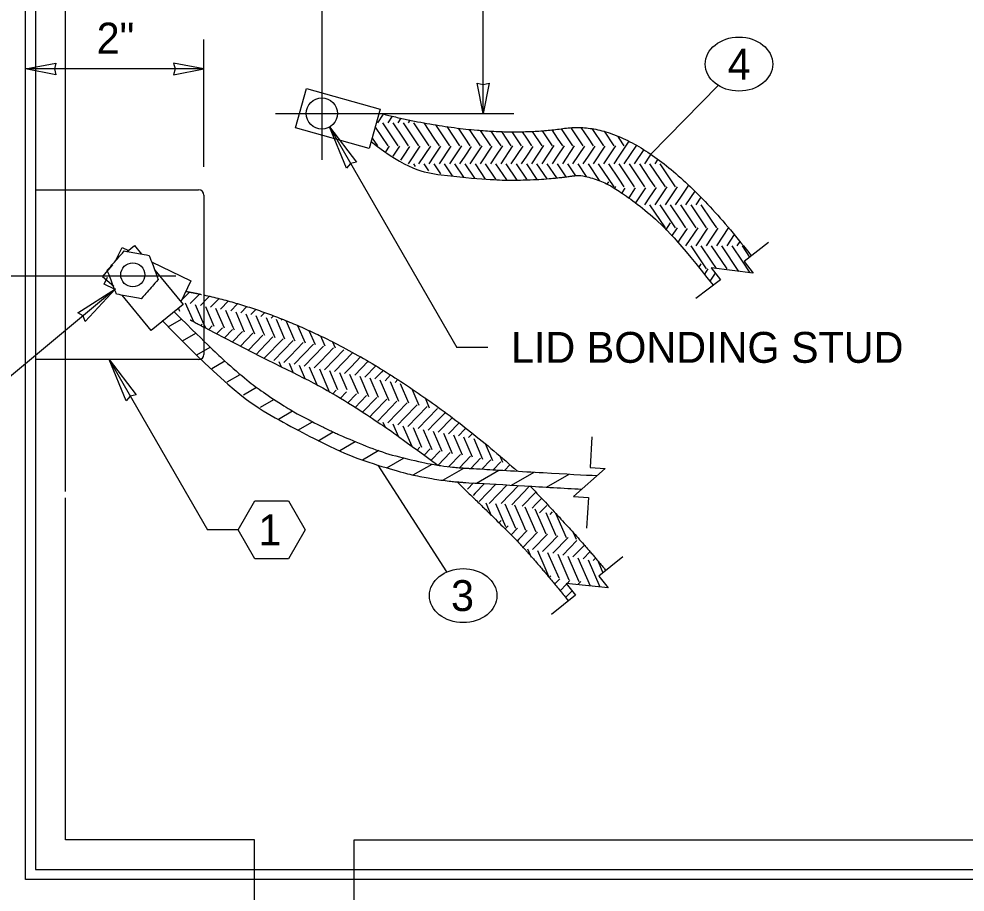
# Model space of a CAD drawing. Extents: x 99862 to 103151, y 100000 to 102076.
# Drawn here: x 101148.1 to 101638.2, y 101390 to 101842.6 of the extents above; entities that cross this region are included whole.
import ezdxf

# ---------------------------------------------------------------- set-up
doc = ezdxf.new("R2010")
doc.units = 0
for name, color, linetype in [('Level 15', 7, 'Continuous'), ('Level 16', 7, 'Continuous'), ('Level 18', 7, 'Continuous'), ('Level 2', 7, 'Continuous'), ('Level 20', 7, 'Continuous'), ('Level 26', 7, 'Continuous'), ('Level 28', 7, 'Continuous'), ('Level 3', 7, 'Continuous'), ('Level 7', 7, 'Continuous')]:
    doc.layers.add(name, color=color, linetype=linetype)

msp = doc.modelspace()

# ---------------------------------------------------------------- linework, layer by layer
at = {"layer": 'Level 15'}
for p, q in [((101388.54, 101793.52), (101388.54, 101912.13)), ((101305.14, 101769.47), (101305.14, 101888.08)), ((101243.99, 101765.95), (101243.99, 101831.95)), ((101243.99, 101816.61), (101151.56, 101816.61)), ((101510.28, 101808.11), (101475.36, 101772.46)), ((101280.97, 101793.52), (101404.54, 101793.52)), ((101309.05, 101786.55), (101375, 101672.31)), ((101229.35, 101709.29), (100983.06, 101709.29)), ((101198.13, 101702.58), (101041.53, 101572.52)), ((101391, 101672.31), (101375, 101672.31)), ((101194.82, 101665.95), (101245.74, 101577.75)), ((101369.79, 101555.93), (101334.19, 101611.25)), ((101261.74, 101577.75), (101245.74, 101577.75))]:
    msp.add_line(p, q, dxfattribs=at)
for points in [[(101151.56, 101816.61), (101167.29, 101819.69), (101166.56, 101816.61), (101167.29, 101813.52)], [(101243.99, 101816.61), (101228.27, 101819.69), (101229, 101816.61), (101228.27, 101813.52)], [(101388.54, 101793.52), (101385.45, 101809.24), (101388.54, 101808.52), (101391.62, 101809.24)], [(101309.05, 101786.55), (101323.04, 101768.27), (101319.93, 101767.69), (101317.88, 101765.28)], [(101198.13, 101702.58), (101182.47, 101685.7), (101181.38, 101688.67), (101178.66, 101690.29)], [(101194.82, 101665.95), (101208.82, 101647.67), (101205.71, 101647.09), (101203.65, 101644.68)]]:
    msp.add_lwpolyline(points, close=True, dxfattribs=at)
for points in [[(101536.39, 101726.6), (101523.71, 101716.84), (101528.44, 101710.7), (101506.72, 101713.52), (101511.44, 101707.39), (101498.77, 101697.62)], [(101444.93, 101626.01), (101444.01, 101610.04), (101451.74, 101609.59), (101435.39, 101595.02), (101443.12, 101594.58), (101442.2, 101578.6)], [(101460.86, 101563.79), (101448.42, 101553.72), (101453.3, 101547.7), (101431.52, 101549.99), (101436.39, 101543.97), (101423.96, 101533.9)]]:
    msp.add_lwpolyline(points, dxfattribs=at)
at = {"layer": 'Level 16'}
for points in [[(101204.21, 101722.02), (101207.99, 101725.12), (101211.64, 101720.67)], [(101197.33, 101703.91), (101191.51, 101708.85), (101196.79, 101715.08)], [(101218.48, 101712.35), (101233.15, 101694.47), (101216.72, 101680.98), (101201.66, 101699.34)]]:
    msp.add_lwpolyline(points, dxfattribs=at)
at = {"layer": 'Level 18'}
for p, q in [((101225.47, 101683.02), (101232.33, 101686.99)), ((101232.79, 101675.71), (101239.73, 101679.71)), ((101240.3, 101668.5), (101247.18, 101672.47)), ((101248.03, 101661.41), (101254.76, 101665.3)), ((101256.05, 101654.49), (101262.71, 101658.34)), ((101264.41, 101647.77), (101271.18, 101651.68)), ((101273.22, 101641.31), (101280.23, 101645.36)), ((101282.59, 101635.17), (101289.89, 101639.39)), ((101292.58, 101629.39), (101300.16, 101633.77)), ((101303.16, 101623.96), (101310.96, 101628.46)), ((101314.29, 101618.84), (101322.36, 101623.5)), ((101326.08, 101614.1), (101334.51, 101618.96)), ((101338.69, 101609.83), (101347.63, 101614.99)), ((101352.39, 101606.19), (101362.1, 101611.8)), ((101367.62, 101603.44), (101378.6, 101609.78)), ((101385.07, 101601.97), (101396.77, 101608.72)), ((101403.26, 101600.92), (101414.96, 101607.68)), ((101421.44, 101599.87), (101433.17, 101606.64))]:
    msp.add_line(p, q, dxfattribs=at)
for points in [[(101228.69, 101690.57), (101247.5, 101672.03), (101254.17, 101665.6), (101267.28, 101654.42), (101273.71, 101649.65), (101286.44, 101641.27), (101292.74, 101637.65), (101302.19, 101632.7), (101305.34, 101631.13), (101311.6, 101628.14), (101314.72, 101626.73), (101330.23, 101620.06), (101342.42, 101616.02), (101360.42, 101611.99), (101366.36, 101610.99), (101373.73, 101610.18), (101375.21, 101610.04), (101377.03, 101609.89), (101377.4, 101609.86), (101377.95, 101609.82), (101378.22, 101609.8), (101378.51, 101609.78), (101378.7, 101609.77), (101378.8, 101609.76), (101379.22, 101609.74), (101379.64, 101609.71), (101380.3, 101609.67), (101380.61, 101609.66), (101383.48, 101609.49), (101420.86, 101607.33), (101441.32, 101606.15), (101447.6, 101605.9)], [(101222.31, 101686.26), (101257.42, 101650.1), (101278.28, 101636.57), (101312.51, 101619.16), (101326.13, 101613.58), (101346.34, 101607.54), (101353.04, 101605.91), (101363.04, 101604.08), (101366.36, 101603.58), (101371.33, 101602.97), (101373.8, 101602.71), (101376.69, 101602.48), (101377.92, 101602.39), (101378.75, 101602.34), (101379.23, 101602.31), (101410.06, 101600.53), (101430.09, 101599.37), (101439.65, 101598.82)]]:
    msp.add_open_spline(points, degree=3, dxfattribs=at)
at = {"layer": 'Level 2'}
for p, q in [((101172.19, 101597.59), (101172.19, 101912.13)), ((101172.19, 101417.13), (101172.19, 101594.38)), ((101270.16, 101417.13), (101172.19, 101417.13)), ((101270.16, 101353.87), (101270.16, 101417.13)), ((101321.72, 101417.13), (101868.28, 101417.13)), ((101321.72, 101353.87), (101321.72, 101417.13))]:
    msp.add_line(p, q, dxfattribs=at)
at = {"layer": 'Level 20'}
msp.add_lwpolyline([(101261.74, 101577.75), (101270.4, 101592.75), (101287.72, 101592.75), (101296.37, 101577.75), (101287.72, 101562.76), (101270.4, 101562.76), (101261.74, 101577.75)], dxfattribs=at)
for centre in [(101521.08, 101819.13), (101378.24, 101543.67)]:
    msp.add_ellipse(centre, major_axis=(-17.5, 0), ratio=0.8, dxfattribs=at)
at = {"layer": 'Level 26'}
for p, q in [((101336.82, 101793.23), (101333.84, 101788.76)), ((101341.41, 101792.13), (101339.16, 101788.76)), ((101346.03, 101791.08), (101344.48, 101788.76)), ((101350.68, 101790.08), (101349.8, 101788.76)), ((101332.71, 101786.47), (101339.16, 101776.79)), ((101336.5, 101788.76), (101344.48, 101776.79)), ((101341.82, 101788.76), (101347.14, 101780.78)), ((101347.14, 101788.76), (101355.12, 101776.79)), ((101352.46, 101788.76), (101360.44, 101776.79)), ((101357.83, 101788.68), (101363.1, 101780.78)), ((101363.85, 101787.63), (101371.08, 101776.79)), ((101369.78, 101786.72), (101376.4, 101776.79)), ((101375.62, 101785.94), (101379.06, 101780.78)), ((101381.37, 101785.29), (101387.04, 101776.79)), ((101424.13, 101784.99), (101426.94, 101780.78)), ((101429.06, 101785.57), (101434.92, 101776.79)), ((101433.98, 101786.18), (101440.24, 101776.79)), ((101439.24, 101786.26), (101442.9, 101780.78)), ((101444.95, 101785.69), (101450.88, 101776.79)), ((101331.13, 101780.85), (101331.18, 101780.78)), ((101331.18, 101780.78), (101333.84, 101776.79)), ((101347.14, 101780.78), (101349.8, 101776.79)), ((101363.1, 101780.78), (101365.76, 101776.79)), ((101379.06, 101780.78), (101381.72, 101776.79)), ((101387.03, 101784.78), (101392.36, 101776.79)), ((101392.6, 101784.4), (101395.02, 101780.78)), ((101395.02, 101780.78), (101397.68, 101776.79)), ((101398.09, 101784.16), (101403, 101776.79)), ((101403.48, 101784.05), (101408.32, 101776.79)), ((101408.78, 101784.08), (101410.98, 101780.78)), ((101410.98, 101780.78), (101413.64, 101776.79)), ((101413.99, 101784.25), (101418.96, 101776.79)), ((101419.1, 101784.55), (101424.28, 101776.79)), ((101426.94, 101780.78), (101429.6, 101776.79)), ((101442.9, 101780.78), (101445.56, 101776.79)), ((101451.19, 101784.31), (101456.2, 101776.79)), ((101458.1, 101781.91), (101458.86, 101780.78)), ((101458.86, 101780.78), (101461.52, 101776.79)), ((101339.96, 101776.66), (101338.02, 101773.74)), ((101345.24, 101776.6), (101341.8, 101771.44)), ((101350.49, 101776.5), (101347.14, 101771.47)), ((101355.84, 101776.54), (101349.8, 101767.48)), ((101361.23, 101776.65), (101355.12, 101767.48)), ((101366.48, 101776.54), (101363.1, 101771.47)), ((101371.89, 101776.68), (101365.76, 101767.48)), ((101377.33, 101776.86), (101371.08, 101767.48)), ((101382.39, 101776.46), (101379.06, 101771.47)), ((101387.89, 101776.74), (101381.72, 101767.48)), ((101393.11, 101776.58), (101387.04, 101767.48)), ((101398.55, 101776.76), (101395.02, 101771.47)), ((101403.85, 101776.73), (101397.68, 101767.48)), ((101409.1, 101776.63), (101403, 101767.48)), ((101414.34, 101776.51), (101410.98, 101771.47)), ((101419.91, 101776.88), (101413.64, 101767.48)), ((101425.22, 101776.87), (101418.96, 101767.48)), ((101430.51, 101776.82), (101426.94, 101771.47)), ((101435.81, 101776.79), (101429.6, 101767.48)), ((101441.01, 101776.61), (101434.92, 101767.48)), ((101446.35, 101776.65), (101442.9, 101771.47)), ((101451.69, 101776.67), (101445.56, 101767.48)), ((101457.12, 101776.83), (101450.88, 101767.48)), ((101464.02, 101779.21), (101458.86, 101771.47)), ((101467.94, 101777.12), (101461.52, 101767.48)), ((101347.14, 101771.47), (101345.73, 101769.36)), ((101363.1, 101771.47), (101360.44, 101767.48)), ((101379.06, 101771.47), (101376.4, 101767.48)), ((101395.02, 101771.47), (101392.36, 101767.48)), ((101410.98, 101771.47), (101408.32, 101767.48)), ((101426.94, 101771.47), (101424.28, 101767.48)), ((101442.9, 101771.47), (101440.24, 101767.48)), ((101458.86, 101771.47), (101456.2, 101767.48)), ((101471.74, 101774.83), (101466.84, 101767.48)), ((101474.82, 101771.47), (101472.16, 101767.48)), ((101475.44, 101772.4), (101474.82, 101771.47)), ((101352.46, 101767.48), (101353.42, 101766.03)), ((101357.78, 101767.48), (101360.21, 101763.84)), ((101363.1, 101767.48), (101366.55, 101762.31)), ((101368.42, 101767.48), (101372.58, 101761.23)), ((101373.74, 101767.48), (101378.41, 101760.48)), ((101379.06, 101767.48), (101384.09, 101759.94)), ((101384.38, 101767.48), (101389.68, 101759.53)), ((101389.7, 101767.48), (101395.02, 101759.5)), ((101395.02, 101767.48), (101400.61, 101759.09)), ((101400.34, 101767.48), (101405.96, 101759.05)), ((101405.66, 101767.48), (101410.98, 101759.5)), ((101410.98, 101767.48), (101416.4, 101759.34)), ((101416.3, 101767.48), (101421.51, 101759.67)), ((101421.62, 101767.48), (101426.53, 101760.12)), ((101426.94, 101767.48), (101431.47, 101760.69)), ((101432.26, 101767.48), (101436.38, 101761.29)), ((101437.58, 101767.48), (101442.02, 101760.82)), ((101442.9, 101767.48), (101448.73, 101758.73)), ((101448.22, 101767.48), (101456.2, 101755.51)), ((101453.54, 101767.48), (101458.86, 101759.5)), ((101458.86, 101767.48), (101466.84, 101755.51)), ((101464.18, 101767.48), (101472.16, 101755.51)), ((101469.5, 101767.48), (101474.82, 101759.5)), ((101474.82, 101767.48), (101482.8, 101755.51)), ((101479.06, 101769.85), (101477.48, 101767.48)), ((101480.14, 101767.48), (101488.12, 101755.51)), ((101395.02, 101759.5), (101395.19, 101759.24)), ((101410.98, 101759.5), (101411.22, 101759.13)), ((101453.54, 101758.17), (101452.7, 101756.91)), ((101457.2, 101755.68), (101456.6, 101754.78)), ((101458.86, 101759.5), (101461.52, 101755.51)), ((101474.82, 101759.5), (101477.48, 101755.51)), ((101483.67, 101755.48), (101477.48, 101746.2)), ((101489, 101755.5), (101482.8, 101746.2)), ((101494.96, 101756.46), (101490.78, 101750.19)), ((101461.93, 101754.79), (101460.36, 101752.43)), ((101467.4, 101755.02), (101463.98, 101749.89)), ((101472.68, 101754.96), (101467.51, 101747.21)), ((101478.12, 101755.14), (101474.82, 101750.19)), ((101498.2, 101753.34), (101493.44, 101746.2)), ((101474.82, 101750.19), (101472.16, 101746.2)), ((101474.82, 101746.2), (101482.8, 101734.23)), ((101480.14, 101746.2), (101488.12, 101734.23)), ((101485.46, 101746.2), (101490.78, 101738.22)), ((101490.78, 101750.19), (101488.12, 101746.2)), ((101490.78, 101746.2), (101498.76, 101734.23)), ((101496.1, 101746.2), (101504.08, 101734.23)), ((101501.39, 101750.14), (101498.76, 101746.2)), ((101501.42, 101746.2), (101506.74, 101738.22)), ((101485.46, 101736.89), (101482.97, 101733.15)), ((101490.78, 101738.22), (101493.44, 101734.23)), ((101506.74, 101738.22), (101509.4, 101734.23)), ((101488.99, 101734.2), (101486.12, 101729.9)), ((101494.17, 101734), (101490.78, 101728.91)), ((101499.7, 101734.31), (101493.44, 101724.92)), ((101504.86, 101734.06), (101498.76, 101724.92)), ((101510.19, 101734.08), (101506.74, 101728.91)), ((101515.7, 101734.37), (101509.4, 101724.92)), ((101490.78, 101728.91), (101489.22, 101726.57)), ((101506.74, 101728.91), (101504.08, 101724.92)), ((101518.66, 101730.83), (101514.72, 101724.92)), ((101521.58, 101727.23), (101520.04, 101724.92)), ((101496.1, 101724.92), (101504.08, 101712.95)), ((101501.42, 101724.92), (101506.74, 101716.94)), ((101506.74, 101724.92), (101514.72, 101712.95)), ((101512.06, 101724.92), (101520.88, 101711.68)), ((101517.38, 101724.92), (101522.7, 101716.94)), ((101522.7, 101724.92), (101526.6, 101719.06)), ((101506.74, 101716.94), (101509.23, 101713.2)), ((101522.7, 101716.94), (101526.71, 101710.93)), ((101501.42, 101715.61), (101500.24, 101713.84)), ((101504.99, 101712.99), (101503.16, 101710.24)), ((101506.74, 101707.63), (101506.05, 101706.59)), ((101508.84, 101710.77), (101506.74, 101707.63)), ((101236.53, 101701), (101232.24, 101696.55)), ((101241.69, 101699.97), (101236.88, 101695)), ((101245.45, 101697.49), (101242.12, 101694.04)), ((101246.78, 101698.87), (101245.45, 101697.49)), ((101251.8, 101697.69), (101247.35, 101693.09)), ((101230.74, 101692.49), (101231.31, 101691.15)), ((101234.27, 101695.47), (101238.48, 101685.73)), ((101239.5, 101694.52), (101243.31, 101685.72)), ((101244.74, 101693.57), (101249.15, 101683.37)), ((101249.97, 101692.62), (101254.38, 101682.41)), ((101256.7, 101696.4), (101252.59, 101692.14)), ((101261.15, 101694.64), (101257.82, 101691.19)), ((101261.48, 101694.98), (101261.15, 101694.64)), ((101266.23, 101693.53), (101263.06, 101690.24)), ((101270.9, 101691.99), (101268.29, 101689.29)), ((101255.2, 101691.67), (101259.01, 101682.86)), ((101260.44, 101690.71), (101264.87, 101680.46)), ((101265.67, 101689.76), (101270.15, 101679.42)), ((101270.91, 101688.81), (101274.71, 101680.01)), ((101275.51, 101690.39), (101273.52, 101688.34)), ((101276.14, 101687.86), (101280.62, 101677.51)), ((101280.05, 101688.72), (101278.76, 101687.38)), ((101281.38, 101686.91), (101285.77, 101676.75)), ((101284.52, 101686.98), (101283.99, 101686.43)), ((101243.07, 101684.41), (101242.35, 101683.66)), ((101243.31, 101685.72), (101244.75, 101682.38)), ((101248.31, 101683.46), (101246.42, 101681.5)), ((101253.54, 101682.51), (101250.51, 101679.37)), ((101259.01, 101682.86), (101259.61, 101681.48)), ((101286.61, 101685.96), (101290.42, 101677.15)), ((101292.4, 101683.72), (101296.32, 101674.65)), ((101258.77, 101681.55), (101254.61, 101677.24)), ((101264.01, 101680.6), (101258.73, 101675.13)), ((101269.24, 101679.65), (101262.85, 101673.03)), ((101274.48, 101678.7), (101266.98, 101670.93)), ((101279.71, 101677.75), (101273.05, 101670.85)), ((101274.71, 101680.01), (101275.31, 101678.62)), ((101290.42, 101677.15), (101291.02, 101675.75)), ((101298.37, 101681.07), (101301.51, 101673.82)), ((101304.42, 101678.23), (101306.12, 101674.3)), ((101284.94, 101676.8), (101275.24, 101666.75)), ((101290.18, 101675.84), (101280.19, 101665.49)), ((101295.41, 101674.89), (101288.75, 101667.99)), ((101300.65, 101673.94), (101290.66, 101663.59)), ((101305.88, 101672.99), (101295.89, 101662.64)), ((101306.12, 101674.3), (101306.63, 101673.13)), ((101310.55, 101675.19), (101311.94, 101672)), ((101273.05, 101670.85), (101271.11, 101668.84)), ((101288.75, 101667.99), (101285.42, 101664.54)), ((101311.12, 101672.04), (101304.45, 101665.14)), ((101316.35, 101671.09), (101306.36, 101660.74)), ((101321.08, 101669.62), (101311.59, 101659.79)), ((101325.08, 101667.38), (101320.16, 101662.28)), ((101282.8, 101665.02), (101283.98, 101662.29)), ((101288.04, 101664.07), (101290.2, 101659.08)), ((101293.27, 101663.12), (101296.44, 101655.79)), ((101304.45, 101665.14), (101301.12, 101661.69)), ((101329.03, 101665.11), (101322.06, 101657.88)), ((101332.95, 101662.79), (101327.29, 101656.93)), ((101298.51, 101662.16), (101302.31, 101653.36)), ((101303.74, 101661.21), (101309.08, 101648.88)), ((101308.97, 101660.26), (101313.23, 101650.42)), ((101314.21, 101659.31), (101318.02, 101650.51)), ((101320.16, 101662.28), (101316.83, 101658.83)), ((101319.44, 101658.36), (101323.78, 101648.33)), ((101335.86, 101659.43), (101332.53, 101655.98)), ((101336.83, 101660.43), (101335.86, 101659.43)), ((101340.67, 101658.04), (101337.76, 101655.03)), ((101302.31, 101653.36), (101302.73, 101652.4)), ((101324.68, 101657.41), (101329.21, 101646.92)), ((101329.91, 101656.46), (101334.18, 101646.58)), ((101335.15, 101655.5), (101339.75, 101644.87)), ((101340.38, 101654.55), (101344.74, 101644.47)), ((101344.48, 101655.61), (101343, 101654.08)), ((101345.61, 101653.6), (101349.97, 101643.52)), ((101348.25, 101653.14), (101348.23, 101653.13)), ((101312.54, 101650.15), (101310.52, 101648.06)), ((101317.78, 101649.2), (101314.48, 101645.79)), ((101323.01, 101648.25), (101318.41, 101643.48)), ((101351.6, 101650.9), (101355.32, 101642.31)), ((101328.25, 101647.3), (101322.29, 101641.13)), ((101333.48, 101646.34), (101326.15, 101638.75)), ((101338.71, 101645.39), (101332.05, 101638.49)), ((101343.95, 101644.44), (101333.96, 101634.09)), ((101349.18, 101643.49), (101339.19, 101633.14)), ((101358.47, 101646.18), (101360.68, 101641.06)), ((101332.05, 101638.49), (101329.96, 101636.32)), ((101354.42, 101642.54), (101347.76, 101635.64)), ((101359.65, 101641.59), (101349.66, 101631.24)), ((101364.89, 101640.63), (101354.89, 101630.28)), ((101369.03, 101638.55), (101363.46, 101632.78)), ((101336.57, 101633.62), (101337.6, 101631.24)), ((101347.76, 101635.64), (101344.43, 101632.19)), ((101372.6, 101635.88), (101365.36, 101628.38)), ((101376.14, 101633.18), (101370.6, 101627.43)), ((101341.81, 101632.66), (101344.52, 101626.38)), ((101347.07, 101631.67), (101351.61, 101621.16)), ((101352.28, 101630.76), (101356.68, 101620.57)), ((101357.53, 101629.77), (101362.03, 101619.37)), ((101363.46, 101632.78), (101360.13, 101629.33)), ((101362.77, 101628.81), (101367.2, 101618.58)), ((101379.16, 101629.93), (101375.83, 101626.48)), ((101379.66, 101630.44), (101379.16, 101629.93)), ((101367.98, 101627.91), (101372.55, 101617.35)), ((101373.24, 101626.91), (101377.67, 101616.67)), ((101378.47, 101625.96), (101382.93, 101615.64)), ((101383.15, 101627.69), (101381.06, 101625.53)), ((101383.68, 101625.05), (101388.29, 101614.4)), ((101355.87, 101620.61), (101354.42, 101619.11)), ((101361.1, 101619.66), (101358.03, 101616.47)), ((101366.34, 101618.7), (101361.63, 101613.82)), ((101389.64, 101622.43), (101393.43, 101613.67)), ((101371.57, 101617.75), (101365.31, 101611.27)), ((101376.81, 101616.8), (101370.74, 101610.52)), ((101382.04, 101615.85), (101376.34, 101609.95)), ((101387.28, 101614.9), (101382.13, 101609.57)), ((101392.51, 101613.95), (101387.96, 101609.23)), ((101397.19, 101616.12), (101398.63, 101612.8)), ((101397.74, 101612.99), (101393.79, 101608.9)), ((101402.51, 101611.56), (101399.61, 101608.56)), ((101383.53, 101602.06), (101380.42, 101598.83)), ((101389.36, 101601.72), (101384.53, 101596.72)), ((101395.19, 101601.39), (101386.48, 101592.37)), ((101401.02, 101601.05), (101391.67, 101591.36)), ((101406.89, 101600.76), (101397.88, 101591.42)), ((101412.13, 101599.81), (101403.41, 101590.78)), ((101384.53, 101596.72), (101383.47, 101595.61)), ((101415.73, 101597.17), (101408.88, 101590.07)), ((101418.65, 101593.82), (101415.94, 101591.01)), ((101389.99, 101591.76), (101392.8, 101585.24)), ((101394.94, 101591.46), (101400.11, 101579.5)), ((101399.83, 101591.29), (101405.35, 101578.55)), ((101404.9, 101590.72), (101408.68, 101582)), ((101410.15, 101589.75), (101415.81, 101576.65)), ((101415.94, 101591.01), (101413.91, 101588.91)), ((101421.52, 101590.42), (101417.84, 101586.61)), ((101415.43, 101588.69), (101421.05, 101575.7)), ((101421.11, 101586.7), (101424.38, 101579.14)), ((101424.38, 101587.01), (101423.07, 101585.65)), ((101426.06, 101586.4), (101431.52, 101573.79)), ((101397.97, 101582.59), (101396.73, 101581.31)), ((101401.47, 101579.84), (101399.83, 101578.15)), ((101408.68, 101582), (101410.58, 101577.6)), ((101424.38, 101579.14), (101426.28, 101574.74)), ((101406.4, 101578.58), (101402.9, 101574.96)), ((101411.4, 101577.39), (101407.01, 101572.84)), ((101416.74, 101576.54), (101408.96, 101568.49)), ((101421.89, 101575.5), (101414.15, 101567.49)), ((101427.28, 101574.72), (101422.71, 101569.98)), ((101435.24, 101576.34), (101436.75, 101572.84)), ((101407.01, 101572.84), (101405.95, 101571.74)), ((101422.71, 101569.98), (101419.38, 101566.53)), ((101432.56, 101573.81), (101424.62, 101565.58)), ((101437.13, 101572.17), (101429.85, 101564.63)), ((101440.84, 101569.65), (101438.42, 101567.13)), ((101411.53, 101567.96), (101413.42, 101563.59)), ((101416.77, 101567.01), (101420.57, 101558.21)), ((101422, 101566.06), (101427.71, 101552.85)), ((101427.23, 101565.11), (101432.94, 101551.9)), ((101438.42, 101567.13), (101435.09, 101563.68)), ((101443.94, 101566.48), (101440.32, 101562.73)), ((101432.47, 101564.16), (101436.28, 101555.35)), ((101437.7, 101563.2), (101443.98, 101548.68)), ((101442.94, 101562.25), (101449.04, 101548.15)), ((101446.83, 101563.1), (101445.55, 101561.78)), ((101448.17, 101561.3), (101450.66, 101555.54)), ((101420.57, 101558.21), (101422.48, 101553.81)), ((101436.28, 101555.35), (101438.18, 101550.95)), ((101423.56, 101553.86), (101422.71, 101552.99)), ((101428.32, 101552.43), (101425.59, 101549.59)), ((101433.54, 101551.45), (101432.07, 101549.93)), ((101439.22, 101550.96), (101437.65, 101549.35)), ((101431.79, 101549.65), (101428.44, 101546.18)), ((101434.61, 101546.19), (101431.28, 101542.74))]:
    msp.add_line(p, q, dxfattribs=at)
for points in [[(101329.59, 101775.35), (101291.4, 101786.07), (101297.15, 101806.53)], [(101297.15, 101806.53), (101335.33, 101795.81), (101329.59, 101775.35)], [(101198.15, 101717.13), (101201.57, 101724.16), (101204.86, 101722.56)], [(101216.83, 101716.72), (101237.22, 101706.78), (101231.94, 101695.94)], [(101197.65, 101702.43), (101192.26, 101705.05), (101194.02, 101708.65)]]:
    msp.add_lwpolyline(points, dxfattribs=at)
msp.add_circle((101305.02, 101793.52), 8.05, dxfattribs=at)
for points, degree in [([(101334.75, 101793.75), (101389.87, 101779.87), (101471.98, 101791.82), (101527.48, 101719.74)], 2), ([(101330.63, 101779.07), (101348.79, 101764.48), (101366.98, 101761.34), (101393.12, 101759.19), (101401.72, 101758.91), (101414.27, 101759.2), (101418.4, 101759.41), (101424.51, 101759.91), (101426.53, 101760.11), (101429.55, 101760.45), (101431.05, 101760.63), (101432.79, 101760.86), (101433.66, 101760.98), (101434.03, 101761.03), (101434.28, 101761.07), (101434.48, 101761.1), (101437.42, 101761.53), (101440.67, 101761.37), (101449.53, 101758.69), (101455.07, 101756.05), (101474.26, 101742.92), (101490.18, 101727.2), (101507.68, 101704.48)], 3), ([(101234.58, 101701.36), (101238.67, 101700.62), (101242.73, 101699.75)], 2), ([(101243.99, 101699.48), (101322.37, 101682.41), (101406.37, 101608.17)], 2), ([(101236.77, 101686.66), (101237.86, 101686.07), (101238.95, 101685.48), (101244.04, 101682.76)], 2), ([(101244.04, 101682.76), (101275.21, 101666.25), (101304.85, 101653.05), (101338.53, 101630.66), (101343.08, 101627.47), (101365.05, 101611.31)], 3), ([(101375.07, 101602.61), (101401.8, 101576.83), (101417.36, 101559.91), (101432.69, 101540.98)], 2), ([(101412.96, 101600.36), (101438.65, 101573.35), (101452.12, 101556.71)], 2)]:
    msp.add_open_spline(points, degree=degree, dxfattribs=at)
at = {"layer": 'Level 28'}
for p, q in [((101156.76, 101753.95), (101241.21, 101753.95)), ((101243.96, 101751.2), (101243.96, 101668.7)), ((101241.21, 101665.95), (101156.76, 101665.95))]:
    msp.add_line(p, q, dxfattribs=at)
for centre, start, end in [((101241.21, 101751.2), 0, 90), ((101241.21, 101668.7), 270, 360)]:
    msp.add_arc(centre, 2.75, start, end, dxfattribs=at)
at = {"layer": 'Level 3'}
for p, q in [((101151.56, 101396.5), (101151.56, 101932.75)), ((101156.72, 101927.59), (101156.72, 101401.66)), ((101156.72, 101401.66), (102033.28, 101401.66)), ((102038.44, 101396.5), (101151.56, 101396.5))]:
    msp.add_line(p, q, dxfattribs=at)
at = {"layer": 'Level 7'}
msp.add_circle((101207.11, 101709.92), 6.24, dxfattribs=at)
for points in [[(101193.93, 101712.32), (101195.38, 101713.98), (101196.86, 101715.66), (101199.77, 101718.99), (101201.23, 101720.65), (101202.68, 101722.3)], [(101202.68, 101722.3), (101204.82, 101721.91), (101206.99, 101721.52), (101211.31, 101720.73), (101213.48, 101720.34), (101215.62, 101719.95)], [(101215.62, 101719.95), (101216.39, 101717.88), (101217.18, 101715.79), (101218.74, 101711.65), (101219.52, 101709.58), (101220.29, 101707.53)], [(101198.61, 101699.9), (101197.83, 101701.96), (101197.04, 101704.06), (101195.48, 101708.2), (101194.7, 101710.26), (101193.93, 101712.32)], [(101220.29, 101707.53), (101218.84, 101705.87), (101217.37, 101704.19), (101214.45, 101700.86), (101212.99, 101699.2), (101211.54, 101697.54)], [(101211.54, 101697.54), (101209.41, 101697.93), (101207.24, 101698.33), (101202.92, 101699.11), (101200.75, 101699.51), (101198.61, 101699.9)]]:
    msp.add_open_spline(points, degree=3, dxfattribs=at)

# ---------------------------------------------------------------- texts
at = {"layer": 'Level 20'}
for s, p in [('2"', (101188.41, 101824.61)), ('LID BONDING STUD', (101403, 101664.32))]:
    msp.add_text(s, height=16, rotation=360, dxfattribs=at).set_placement(p)
for s, p in [('4', (101515.24, 101811.13)), ('1', (101272.19, 101569.76)), ('3', (101371.95, 101535.67))]:
    msp.add_text(s, height=16, dxfattribs=at).set_placement(p)

doc.saveas('drawing.dxf')
